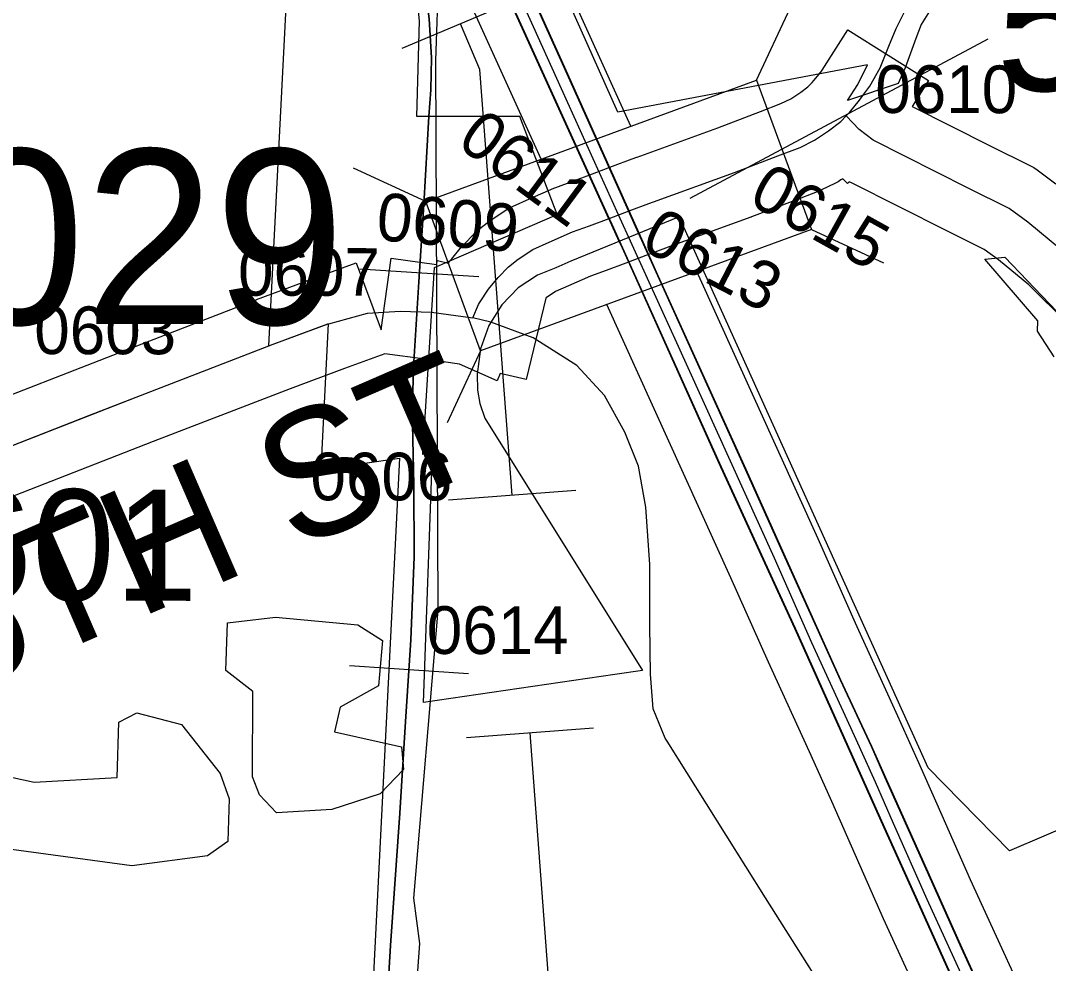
# Model space of a CAD drawing. Extents: x -157.2 to -99.3, y 12.2 to 46.2.
# Drawn here: x -146.56 to -145.913, y 28.305 to 28.898 of the extents above; entities that cross this region are included whole.
import ezdxf

# ---------------------------------------------------------------- set-up
doc = ezdxf.new("R2010")
doc.units = 0
for name, color, linetype in [('tdCoCityStreetMajor', 7, 'Continuous'), ('tdCoCityStreetMinor', 7, 'Continuous'), ('tdCoCorpBndry', 7, 'Continuous'), ('tdCoDivCarto', 7, 'Continuous'), ('tdCoHydroRiver', 7, 'Continuous'), ('tdCoInt', 7, 'Continuous'), ('tdCoIntCL', 7, 'Continuous'), ('tdCoIntRte', 7, 'Continuous'), ('tdCoPipe', 7, 'Continuous'), ('tdCoRRCL', 7, 'Continuous'), ('tdCoSecRdNmbr', 7, 'Continuous'), ('tdCoSecRdTxt', 7, 'Continuous'), ('tdCoSecRteBand', 7, 'Continuous'), ('tdCoSecRteCL', 7, 'Continuous'), ('tdCoStrucNonDivPri', 7, 'Continuous'), ('tdCoStrucPriMaintName', 7, 'Continuous'), ('tdCoStrucSecFHWANum', 7, 'Continuous'), ('tdCoSurfAsphalt', 7, 'Continuous'), ('tdCoSurfConc', 7, 'Continuous'), ('tdCoSurfGravel', 7, 'Continuous')]:
    doc.layers.add(name, color=color, linetype=linetype)

msp = doc.modelspace()

# ---------------------------------------------------------------- linework, layer by layer
at = {"layer": 'tdCoCityStreetMajor'}
for points in [[(-146.40368, 28.69321), (-146.38507, 29.05461), (-146.38791, 29.07414), (-146.39421, 29.09778), (-146.40807, 29.12991), (-146.50732, 29.34732)], [(-146.03004, 28.85087), (-146.02553, 28.85668), (-146.01906, 28.86829), (-146.01361, 28.88186), (-146.00903, 28.89299), (-146.00059, 28.90979), (-146.0073, 28.91492), (-146.01132, 28.91942), (-146.01337, 28.92471), (-146.01662, 28.95438), (-146.01717, 28.9679), (-146.01859, 29.00992)], [(-146.3658, 28.70726), (-146.34154, 28.7138), (-146.32102, 28.71518), (-146.30118, 28.71456)], [(-146.15299, 28.44453), (-146.15421, 28.44647), (-146.16181, 28.46483), (-146.16359, 28.48672), (-146.16398, 28.5175), (-146.16398, 28.55577), (-146.16635, 28.59188), (-146.17108, 28.61752), (-146.17957, 28.63903), (-146.19239, 28.66211), (-146.20995, 28.68085), (-146.23737, 28.69841), (-146.26387, 28.70819)], [(-146.00883, 28.21398), (-146.04824, 28.27806), (-146.09115, 28.34587), (-146.15299, 28.44453)]]:
    msp.add_lwpolyline(points, dxfattribs=at)
at = {"layer": 'tdCoCityStreetMinor'}
for p, q in [((-146.36639, 28.70708), (-146.36621, 28.70715)), ((-146.36621, 28.70715), (-146.3658, 28.70726))]:
    msp.add_line(p, q, dxfattribs=at)
at = {"layer": 'tdCoCorpBndry'}
for points in [[(-145.85042, 28.94497), (-145.92371, 28.9452), (-145.93217, 28.94377), (-145.94107, 28.94131), (-145.9502, 28.93765), (-145.95777, 28.93364), (-145.96446, 28.92923), (-145.96991, 28.92477), (-145.98411, 28.90929), (-145.98904, 28.90231), (-145.99322, 28.89552), (-145.99651, 28.88667), (-146.00328, 28.86831), (-146.00765, 28.85837), (-146.03957, 28.84774), (-146.03315, 28.85771), (-146.02711, 28.87019), (-146.04355, 28.86701), (-146.18415, 28.84046), (-146.34081, 29.19151), (-146.35764, 29.22842), (-146.50979, 29.56621)], [(-145.87283, 28.40315), (-145.93773, 28.37545), (-145.98885, 28.42772), (-146.14544, 28.7745), (-146.21358, 28.74669), (-146.22305, 28.74236), (-146.23467, 28.73786), (-146.24671, 28.72983), (-146.25706, 28.71915), (-146.26512, 28.70619), (-146.2704, 28.69146), (-146.2725, 28.67556), (-146.27238, 28.6655), (-146.27082, 28.65705), (-146.26767, 28.64785), (-146.16858, 28.48899), (-146.186, 28.48643), (-146.30639, 28.46877), (-146.30062, 28.62576), (-146.30674, 28.62486), (-146.29945, 28.74251), (-146.22218, 28.77605), (-146.24561, 28.8376), (-146.31041, 28.83762), (-146.30882, 28.89785), (-146.31183, 28.92565)], [(-146.8055, 28.28288), (-146.80106, 28.37585), (-146.79416, 28.49669), (-146.79288, 28.5293), (-146.78112, 28.52871), (-146.78076, 28.5359), (-146.79305, 28.53651), (-146.79462, 28.54548), (-146.70564, 28.57864), (-146.58332, 28.62353), (-146.51586, 28.64982), (-146.48715, 28.66101), (-146.40083, 28.6943), (-146.36621, 28.70715), (-146.37081, 28.61546), (-146.32143, 28.6227), (-146.34546, 28.14362)]]:
    msp.add_lwpolyline(points, dxfattribs=at)
at = {"layer": 'tdCoDivCarto'}
for points in [[(-146.44427, 29.3356), (-146.42609, 29.29533), (-146.39132, 29.2174), (-146.35541, 29.13915), (-146.32631, 29.07553), (-146.29992, 29.01634), (-146.24616, 28.89797), (-146.18952, 28.77353), (-146.18872, 28.77178), (-146.18299, 28.75918), (-146.18296, 28.75912)], [(-146.44427, 29.3356), (-146.42609, 29.29533), (-146.39132, 29.2174), (-146.35541, 29.13915), (-146.32631, 29.07553), (-146.29992, 29.01634), (-146.24616, 28.89797), (-146.18952, 28.77353), (-146.18872, 28.77178), (-146.18299, 28.75918), (-146.18296, 28.75912)], [(-146.17063, 28.76419), (-146.17608, 28.77639), (-146.17691, 28.77824), (-146.1813, 28.78807), (-146.21558, 28.86427), (-146.25331, 28.94811), (-146.27575, 28.99744), (-146.30534, 29.06328), (-146.33765, 29.13455), (-146.37513, 29.21692), (-146.40127, 29.27487), (-146.41805, 29.31194)], [(-146.17063, 28.76419), (-146.17608, 28.77639), (-146.17691, 28.77824), (-146.1813, 28.78807), (-146.21558, 28.86427), (-146.25331, 28.94811), (-146.27575, 28.99744), (-146.30534, 29.06328), (-146.33765, 29.13455), (-146.37513, 29.21692), (-146.40127, 29.27487), (-146.41805, 29.31194)], [(-146.07938, 28.56222), (-146.10337, 28.61544), (-146.15861, 28.73727), (-146.17063, 28.76419)], [(-146.07938, 28.56222), (-146.10337, 28.61544), (-146.15861, 28.73727), (-146.17063, 28.76419)], [(-146.18296, 28.75912), (-146.18106, 28.75494), (-146.12014, 28.61955), (-146.09136, 28.55677)], [(-146.18296, 28.75912), (-146.18106, 28.75494), (-146.12014, 28.61955), (-146.09136, 28.55677)], [(-146.01547, 28.42149), (-146.02421, 28.44109), (-146.04369, 28.48301), (-146.07938, 28.56222)], [(-146.01547, 28.42149), (-146.02421, 28.44109), (-146.04369, 28.48301), (-146.07938, 28.56222)], [(-146.09136, 28.55677), (-146.07255, 28.51573), (-146.01632, 28.39021), (-145.99482, 28.34239)], [(-146.09136, 28.55677), (-146.07255, 28.51573), (-146.01632, 28.39021), (-145.99482, 28.34239)], [(-145.93633, 28.24586), (-145.96749, 28.31434), (-145.99166, 28.3681), (-146.01547, 28.42149)], [(-145.93633, 28.24586), (-145.96749, 28.31434), (-145.99166, 28.3681), (-146.01547, 28.42149)], [(-145.99482, 28.34239), (-145.95812, 28.26074), (-145.91684, 28.16892)], [(-145.99482, 28.34239), (-145.95812, 28.26074), (-145.91684, 28.16892)]]:
    msp.add_lwpolyline(points, dxfattribs=at)
at = {"layer": 'tdCoHydroRiver'}
for points in [[(-145.90955, 28.68649), (-145.92006, 28.70263), (-145.91986, 28.70894), (-145.95331, 28.74795), (-145.94064, 28.74911), (-145.87044, 28.67572), (-145.79963, 28.57231), (-145.76268, 28.49528), (-145.69742, 28.28978)], [(-146.39878, 28.39942), (-146.40946, 28.41083), (-146.41383, 28.42203), (-146.41365, 28.47572), (-146.43058, 28.48891), (-146.4296, 28.51889), (-146.39949, 28.52263), (-146.34756, 28.51776), (-146.3321, 28.50777), (-146.33461, 28.47943), (-146.35872, 28.46601), (-146.36239, 28.45034), (-146.32008, 28.44104), (-146.31897, 28.42679), (-146.33367, 28.41148), (-146.36399, 28.40143), (-146.39878, 28.39942)], [(-146.48984, 28.36611), (-146.59828, 28.38074), (-146.63051, 28.40866), (-146.62379, 28.42107), (-146.59358, 28.42797), (-146.55126, 28.41868), (-146.49907, 28.42168), (-146.49794, 28.4564), (-146.4867, 28.46234), (-146.45852, 28.45509), (-146.43428, 28.42428), (-146.42848, 28.4083), (-146.42936, 28.38148), (-146.44228, 28.37243), (-146.48984, 28.36611)]]:
    msp.add_lwpolyline(points, dxfattribs=at)
at = {"layer": 'tdCoInt'}
for points in [[(-146.23236, 28.81073), (-146.34337, 29.05557), (-146.41985, 29.22257), (-146.46686, 29.32724), (-146.55382, 29.52034), (-146.57131, 29.56446), (-146.58365, 29.59655), (-146.58811, 29.61328), (-146.59808, 29.65438), (-146.60063, 29.66489), (-146.60662, 29.70777), (-146.60853, 29.72254), (-146.60943, 29.76166), (-146.60688, 29.85155), (-146.60614, 29.87381), (-146.60434, 29.93772), (-146.60182, 30.00477), (-146.60049, 30.04074)], [(-146.17587, 28.83145), (-146.28877, 29.08045), (-146.36521, 29.24735), (-146.41214, 29.35185), (-146.49855, 29.54373), (-146.51542, 29.58629), (-146.5265, 29.61511), (-146.52996, 29.62808), (-146.53977, 29.66853), (-146.54162, 29.67614), (-146.54716, 29.71577), (-146.54862, 29.72709), (-146.54941, 29.7615), (-146.5469, 29.84972), (-146.54617, 29.87197), (-146.54437, 29.93575), (-146.54187, 30.00252), (-146.54082, 30.03043)], [(-145.40573, 27.31251), (-145.50322, 27.48528), (-145.52352, 27.52184), (-145.55625, 27.58075), (-145.63213, 27.71614), (-145.6656, 27.77479), (-145.78521, 27.9882), (-145.79382, 28.00432), (-145.80785, 28.02913), (-145.8221, 28.05617), (-145.82712, 28.06548), (-145.83629, 28.08378), (-145.86724, 28.14764), (-145.88342, 28.18411), (-145.90306, 28.22728), (-145.91548, 28.25538), (-145.96217, 28.35723), (-145.98314, 28.40488), (-145.99462, 28.43094), (-146.00788, 28.46036), (-146.0346, 28.51881), (-146.05815, 28.5719), (-146.13446, 28.74013)], [(-145.45785, 27.28278), (-145.55557, 27.45597), (-145.60864, 27.55152), (-145.68435, 27.6866), (-145.71782, 27.74525), (-145.83786, 27.95941), (-145.8464, 27.97542), (-145.86052, 28.00037), (-145.87504, 28.02795), (-145.88035, 28.03778), (-145.89011, 28.05725), (-145.92168, 28.12238), (-145.93815, 28.15952), (-145.9578, 28.20272), (-145.9702, 28.23075), (-146.0169, 28.33264), (-146.04943, 28.40653), (-146.06251, 28.43557), (-146.0893, 28.49417), (-146.1129, 28.54734), (-146.19094, 28.71941)]]:
    msp.add_lwpolyline(points, dxfattribs=at)
at = {"layer": 'tdCoIntCL'}
msp.add_lwpolyline([(-145.94284, 28.24306), (-145.98953, 28.34494), (-146.0106, 28.39279), (-146.02203, 28.41874), (-146.03519, 28.44797), (-146.06195, 28.50649), (-146.08553, 28.55962), (-146.14914, 28.69987), (-146.14931, 28.70025), (-146.1836, 28.77584), (-146.21952, 28.85507), (-146.23717, 28.89401), (-146.31607, 29.06801), (-146.38561, 29.21985), (-146.38561, 29.21985), (-146.39253, 29.23496), (-146.4395, 29.33955)], dxfattribs=at)
at = {"layer": 'tdCoIntRte'}
for points in [[(-146.42647, 29.29533), (-146.3917, 29.2174), (-146.35579, 29.13915), (-146.32669, 29.07553), (-146.3003, 29.01634), (-146.24654, 28.89797), (-146.1899, 28.77353), (-146.18968, 28.77306), (-146.1891, 28.77178), (-146.18337, 28.75918), (-146.18334, 28.75912), (-146.18143, 28.75494), (-146.12052, 28.61955), (-146.09174, 28.55677), (-146.07293, 28.51573), (-146.0167, 28.39021), (-145.9952, 28.34239), (-145.9585, 28.26074)], [(-146.42647, 29.29533), (-146.3917, 29.2174), (-146.35579, 29.13915), (-146.32669, 29.07553), (-146.3003, 29.01634), (-146.24654, 28.89797), (-146.1899, 28.77353), (-146.1891, 28.77178), (-146.18337, 28.75918), (-146.18334, 28.75912), (-146.18143, 28.75494), (-146.12052, 28.61955), (-146.09174, 28.55677), (-146.07293, 28.51573), (-146.0167, 28.39021), (-145.9952, 28.34239), (-145.9585, 28.26074)], [(-145.9367, 28.24586), (-145.96787, 28.31434), (-145.99204, 28.3681), (-146.01585, 28.42149), (-146.02459, 28.44109), (-146.04407, 28.48301), (-146.07976, 28.56222), (-146.10375, 28.61544), (-146.15899, 28.73727), (-146.17101, 28.76419), (-146.17646, 28.77639), (-146.17729, 28.77824), (-146.17744, 28.77859), (-146.18168, 28.78807), (-146.21595, 28.86427), (-146.25368, 28.94811), (-146.27613, 28.99744), (-146.30572, 29.06328), (-146.33802, 29.13455), (-146.37551, 29.21692), (-146.40165, 29.27487)], [(-145.9367, 28.24586), (-145.96787, 28.31434), (-145.99204, 28.3681), (-146.01585, 28.42149), (-146.02459, 28.44109), (-146.04407, 28.48301), (-146.07976, 28.56222), (-146.10375, 28.61544), (-146.15899, 28.73727), (-146.17101, 28.76419), (-146.17646, 28.77639), (-146.17729, 28.77824), (-146.18168, 28.78807), (-146.21595, 28.86427), (-146.25368, 28.94811), (-146.27613, 28.99744), (-146.30572, 29.06328), (-146.33802, 29.13455), (-146.37551, 29.21692), (-146.40165, 29.27487)]]:
    msp.add_lwpolyline(points, dxfattribs=at)
at = {"layer": 'tdCoPipe'}
for p, q in [((-146.2461, 28.91162), (-146.31991, 28.88034)), ((-146.21059, 28.60226), (-146.29053, 28.59623)), ((-146.19929, 28.45269), (-146.27923, 28.44666))]:
    msp.add_line(p, q, dxfattribs=at)
for points in [[(-146.25056, 28.59925), (-146.27078, 28.86714), (-146.283, 28.89598)], [(-146.21668, 28.15052), (-146.23926, 28.44967)]]:
    msp.add_lwpolyline(points, dxfattribs=at)
at = {"layer": 'tdCoRRCL'}
for p, q in [((-146.27142, 28.73682), (-146.34627, 28.74165)), ((-146.27805, 28.48695), (-146.35288, 28.49197))]:
    msp.add_line(p, q, dxfattribs=at)
for points in [[(-146.01036, 26.40132), (-146.074, 26.48393), (-146.19745, 26.57165), (-146.27806, 26.66588), (-146.31169, 26.7491), (-146.31876, 26.77459), (-146.31365, 27.91309), (-146.32129, 28.01915), (-146.33208, 28.07636), (-146.32252, 28.12816), (-146.30853, 28.31722), (-146.31235, 28.34578), (-146.29705, 28.5269), (-146.29854, 28.87281), (-146.29676, 28.92802), (-146.59974, 29.61697)], [(-146.46231, 29.29658), (-146.42089, 29.20536), (-146.38183, 29.11859), (-146.35404, 29.05567), (-146.33831, 29.02107), (-146.32835, 28.99879), (-146.31996, 28.97572), (-146.31315, 28.95291), (-146.30581, 28.92355), (-146.30266, 28.89918), (-146.30135, 28.87453), (-146.30161, 28.85435), (-146.30293, 28.83761), (-146.30607, 28.78226), (-146.30922, 28.7335), (-146.31289, 28.67662), (-146.31315, 28.64411), (-146.31236, 28.60584), (-146.3121, 28.56049), (-146.3142, 28.50832), (-146.31787, 28.45354), (-146.32128, 28.39927), (-146.32704, 28.31591), (-146.33045, 28.25981)], [(-146.33045, 28.25981), (-146.32704, 28.31591), (-146.32128, 28.39927), (-146.31787, 28.45354), (-146.3142, 28.50832), (-146.3121, 28.56049), (-146.31236, 28.60584), (-146.31315, 28.64411), (-146.31289, 28.67662), (-146.30922, 28.7335), (-146.30607, 28.78226), (-146.30293, 28.83761), (-146.30161, 28.85435), (-146.30135, 28.87453), (-146.30266, 28.89918), (-146.30581, 28.92355), (-146.31315, 28.95291), (-146.31996, 28.97572), (-146.32835, 28.99879), (-146.33831, 29.02107), (-146.35404, 29.05567), (-146.38183, 29.11859), (-146.42089, 29.20536), (-146.46231, 29.29658)]]:
    msp.add_lwpolyline(points, dxfattribs=at)
at = {"layer": 'tdCoSecRteBand'}
for points in [[(-146.59394, 28.65159), (-146.49804, 28.68896), (-146.49799, 28.68898), (-146.49794, 28.689), (-146.41447, 28.7212), (-146.41163, 28.72229), (-146.41145, 28.72236), (-146.41127, 28.72243), (-146.37682, 28.73521), (-146.3487, 28.74564), (-146.33303, 28.70342), (-146.32672, 28.74843), (-146.29821, 28.74444), (-146.29758, 28.74708), (-146.29058, 28.74541), (-146.28975, 28.74671), (-146.28855, 28.74815), (-146.28239, 28.75554), (-146.2817, 28.75637), (-146.28095, 28.75715), (-146.27454, 28.76381), (-146.27319, 28.76521), (-146.27167, 28.76642), (-146.2655, 28.77136), (-146.26434, 28.77229), (-146.26309, 28.7731), (-146.25396, 28.77902), (-146.25206, 28.78025), (-146.25, 28.78118), (-146.23965, 28.78587), (-146.23943, 28.78597), (-146.23921, 28.78606), (-146.22441, 28.79247), (-146.22371, 28.79278), (-146.22299, 28.79305), (-146.21236, 28.79702), (-146.20002, 28.80163), (-146.18741, 28.80634), (-146.175, 28.81098), (-146.17219, 28.81204), (-146.17204, 28.81209), (-146.1719, 28.81214), (-146.1211, 28.83055), (-146.09426, 28.84079), (-146.08144, 28.84574), (-146.07528, 28.84874), (-146.06897, 28.85294), (-146.06455, 28.85636), (-146.06183, 28.85904), (-146.06074, 28.86019), (-146.05627, 28.86552), (-146.05543, 28.86685), (-146.03944, 28.89224), (-145.98867, 28.86027), (-145.99898, 28.84389), (-145.95018, 28.81938), (-145.92455, 28.80657), (-145.92231, 28.80545), (-145.92029, 28.80398), (-145.90846, 28.79535)], [(-145.8767, 28.68318), (-145.92561, 28.73162), (-145.94459, 28.74744), (-145.95362, 28.75402), (-145.97703, 28.76573), (-145.97705, 28.76574), (-145.97708, 28.76575), (-146.037, 28.79584), (-146.03853, 28.7966), (-146.03952, 28.79556), (-146.04254, 28.79845), (-146.04369, 28.79769), (-146.04538, 28.79656), (-146.0472, 28.79567), (-146.05633, 28.79124), (-146.05747, 28.79068), (-146.05865, 28.79022), (-146.07271, 28.7848), (-146.07276, 28.78478), (-146.07281, 28.78476), (-146.09993, 28.7744), (-146.10017, 28.77431), (-146.10042, 28.77422), (-146.15132, 28.75578), (-146.15399, 28.75478), (-146.16641, 28.75014), (-146.17901, 28.74543), (-146.19136, 28.74082), (-146.20126, 28.73711), (-146.21513, 28.7311), (-146.22321, 28.72745), (-146.22919, 28.72357), (-146.2294, 28.7234), (-146.24166, 28.67205), (-146.25801, 28.67595), (-146.26003, 28.67138), (-146.28366, 28.68181), (-146.30535, 28.68485), (-146.33054, 28.68838), (-146.35595, 28.67895), (-146.39022, 28.66624), (-146.39288, 28.66522), (-146.4763, 28.63304), (-146.57243, 28.59558)]]:
    msp.add_lwpolyline(points, dxfattribs=at)
at = {"layer": 'tdCoSecRteCL'}
for p in [(-146.30118, 28.71456), (-146.26387, 28.70819)]:
    msp.add_line(p, (-146.27537, 28.71094), dxfattribs=at)
for points in [[(-146.04046, 28.83798), (-146.03838, 28.84016), (-146.03197, 28.84781), (-146.03004, 28.85087)], [(-146.27537, 28.71094), (-146.27167, 28.71932), (-146.27105, 28.72028), (-146.2655, 28.72894), (-146.25934, 28.73634), (-146.25293, 28.743), (-146.24676, 28.74793), (-146.23764, 28.75385), (-146.22728, 28.75853), (-146.21248, 28.76495), (-146.20186, 28.76892), (-146.18952, 28.77353), (-146.17691, 28.77824), (-146.1645, 28.78288), (-146.16168, 28.78393), (-146.11064, 28.80243), (-146.08351, 28.81279), (-146.06945, 28.81821), (-146.06033, 28.82265), (-146.05145, 28.82857), (-146.0438, 28.83449), (-146.04046, 28.83798)], [(-145.67089, 28.30428), (-145.71898, 28.44287), (-145.73402, 28.48159), (-145.76608, 28.56938), (-145.78803, 28.62166), (-145.79617, 28.63523), (-145.80529, 28.64879), (-145.80624, 28.64994), (-145.80626, 28.64996), (-145.8191, 28.66556), (-145.85387, 28.7028), (-145.8555, 28.7044), (-145.85558, 28.70449), (-145.90542, 28.75384), (-145.92613, 28.77111), (-145.93797, 28.77974), (-145.96361, 28.79256), (-146.02354, 28.82265), (-146.03217, 28.82955), (-146.04046, 28.83798)], [(-146.79305, 28.53652), (-146.79462, 28.54548), (-146.79461, 28.54548), (-146.78973, 28.54659), (-146.70564, 28.57864), (-146.58332, 28.62353), (-146.48715, 28.66101), (-146.40368, 28.69321), (-146.40083, 28.6943), (-146.36639, 28.70708)]]:
    msp.add_lwpolyline(points, dxfattribs=at)
at = {"layer": 'tdCoStrucNonDivPri'}
for p, q in [((-146.09676, 28.86047), (-146.07574, 28.90583)), ((-146.3049, 28.78413), (-146.35027, 28.80515)), ((-146.06233, 28.76658), (-146.01696, 28.74556)), ((-146.27047, 28.69024), (-146.29149, 28.64487))]:
    msp.add_line(p, q, dxfattribs=at)
msp.add_lwpolyline([(-146.3049, 28.78413), (-146.09676, 28.86047), (-146.06233, 28.76658), (-146.27047, 28.69024)], close=True, dxfattribs=at)
at = {"layer": 'tdCoStrucSecFHWANum'}
msp.add_line((-145.95132, 28.88635), (-146.13874, 28.78603), dxfattribs=at)
at = {"layer": 'tdCoSurfAsphalt'}
msp.add_line((-146.26387, 28.70819), (-146.27537, 28.71094), dxfattribs=at)
for points in [[(-146.04046, 28.83798), (-146.03838, 28.84016), (-146.03197, 28.84781), (-146.03004, 28.85087)], [(-146.1645, 28.78288), (-146.16168, 28.78393), (-146.11064, 28.80243), (-146.08351, 28.81279), (-146.06945, 28.81821), (-146.06033, 28.82265), (-146.05145, 28.82857), (-146.0438, 28.83449), (-146.04047, 28.83798)], [(-146.27537, 28.71094), (-146.27167, 28.71932), (-146.27105, 28.72028), (-146.2655, 28.72894), (-146.25934, 28.73634), (-146.25293, 28.743), (-146.24676, 28.74793), (-146.23764, 28.75385), (-146.22728, 28.75853), (-146.21248, 28.76495), (-146.20186, 28.76892)]]:
    msp.add_lwpolyline(points, dxfattribs=at)
at = {"layer": 'tdCoSurfConc'}
msp.add_line((-146.30118, 28.71456), (-146.27537, 28.71094), dxfattribs=at)
msp.add_lwpolyline([(-146.20186, 28.76892), (-146.18952, 28.77353), (-146.17691, 28.77824), (-146.1645, 28.78288)], dxfattribs=at)
at = {"layer": 'tdCoSurfGravel'}
for points in [[(-145.85558, 28.70449), (-145.90542, 28.75384), (-145.92613, 28.77111), (-145.93797, 28.77974), (-145.96361, 28.79256), (-146.02354, 28.82265), (-146.03217, 28.82955), (-146.04046, 28.83798)], [(-146.79461, 28.54548), (-146.78973, 28.54659), (-146.70564, 28.57864), (-146.58332, 28.62353), (-146.48715, 28.66101), (-146.40368, 28.69321), (-146.40083, 28.6943), (-146.36639, 28.70708)]]:
    msp.add_lwpolyline(points, dxfattribs=at)

# ---------------------------------------------------------------- texts
at = {"layer": 'tdCoSecRdNmbr'}
for s, height, rotation, p in [('0610', 0.03, 359.88822, (-146.02214, 28.83988)), ('0611', 0.03, 323.58656, (-146.28635, 28.81981)), ('0615', 0.03, 330.97116, (-146.10297, 28.7834)), ('0609', 0.03, 354.88823, (-146.33672, 28.76002)), ('0613', 0.03, 332.67086, (-146.1707, 28.75477)), ('0607', 0.03, 359.88822, (-146.42299, 28.72493)), ('0603', 0.03, 359.88828, (-146.55118, 28.68815)), ('0606', 0.03, 359.88828, (-146.37745, 28.59614)), ('0601', 0.07, 359.88808, (-146.65675, 28.53323)), ('0614', 0.03, 359.88828, (-146.30427, 28.49945))]:
    msp.add_text(s, height=height, rotation=rotation, dxfattribs=at).set_placement(p)
at = {"layer": 'tdCoSecRdTxt'}
msp.add_text('225TH ST', height=0.08, rotation=23.47113, dxfattribs=at).set_placement((-146.70965, 28.42423))
at = {"layer": 'tdCoStrucPriMaintName'}
msp.add_text('97398O029', height=0.11, dxfattribs=at).set_placement((-147.12476, 28.70695))
at = {"layer": 'tdCoStrucSecFHWANum'}
msp.add_text('53670', height=0.085, dxfattribs=at).set_placement((-145.94627, 28.85383))

doc.saveas('drawing.dxf')
